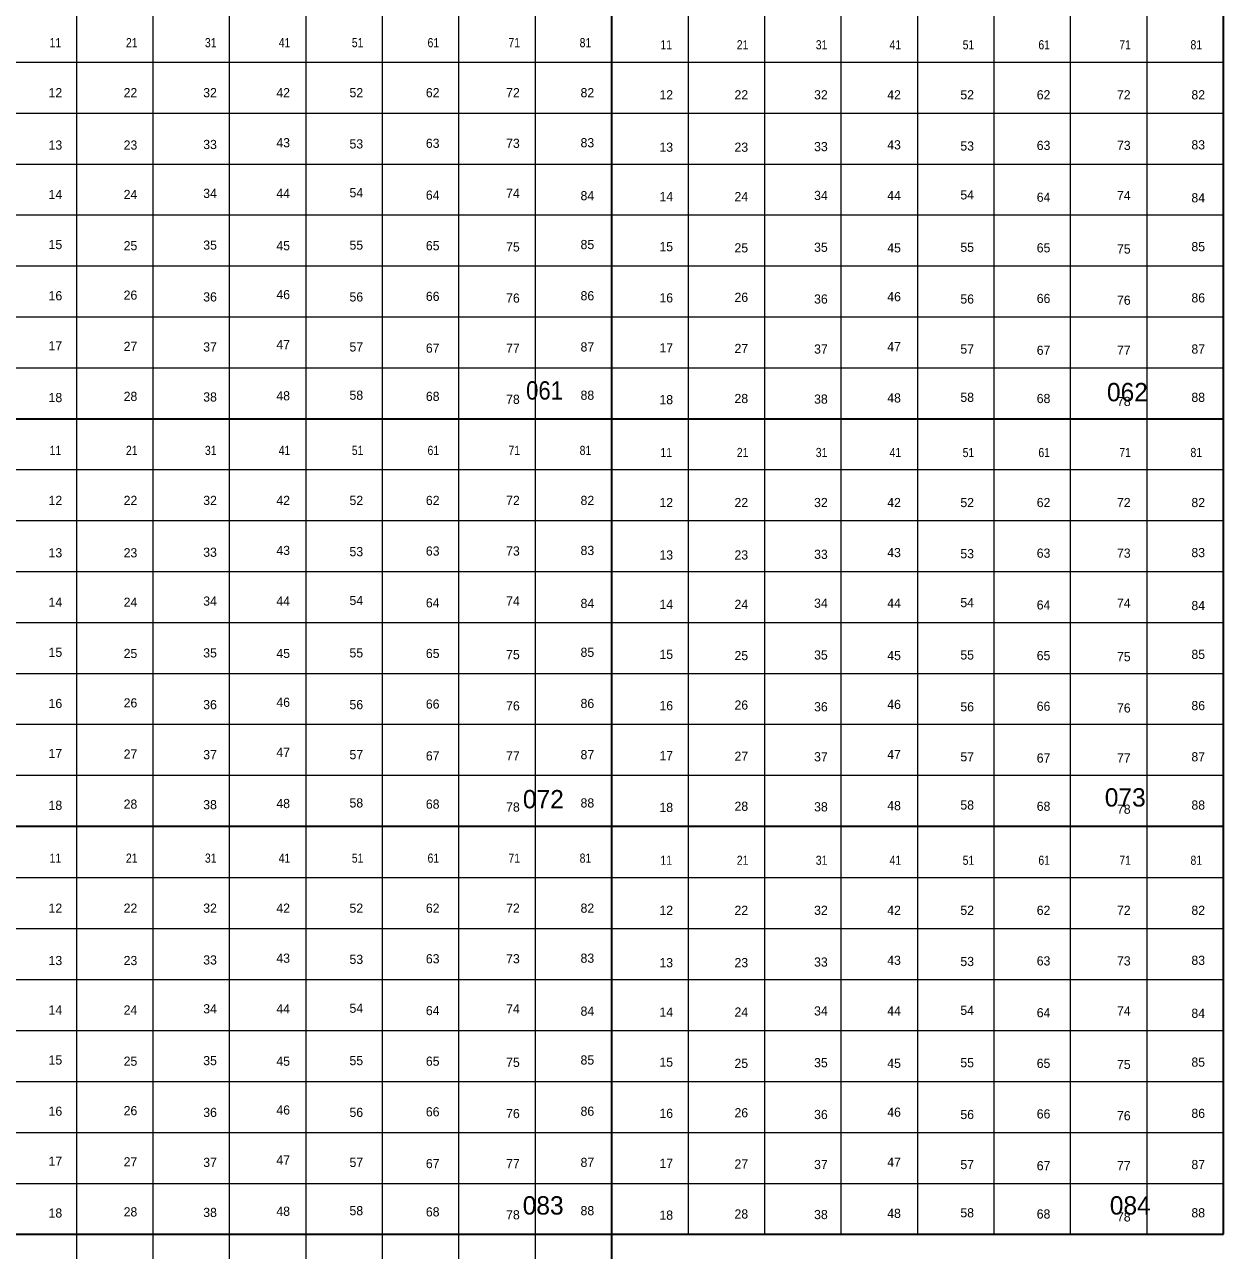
# Model space of a CAD drawing. Extents: x 639000 to 672000, y 222000 to 252000.
# Drawn here: x 666119 to 672000, y 233921 to 239934 of the extents above; entities that cross this region are included whole.
import ezdxf
from ezdxf.enums import TextEntityAlignment as Align

# ---------------------------------------------------------------- set-up
doc = ezdxf.new("R2010")
doc.units = 0
doc.header["$LTSCALE"] = 18
doc.layers.add('1', color=7, linetype='Continuous', lineweight=13)
doc.layers.add('2', color=7, linetype='Continuous')
doc.layers.add('29', color=7, linetype='Continuous')

msp = doc.modelspace()

# ---------------------------------------------------------------- linework, layer by layer
at = {"layer": '1'}
for p, q in [((666375, 230000), (666375, 242000)), ((666750, 230000), (666750, 242000)), ((667125, 230000), (667125, 242000)), ((667500, 230000), (667500, 242000)), ((667875, 230000), (667875, 242000)), ((668250, 230000), (668250, 242000)), ((668625, 230000), (668625, 242000)), ((669375, 234000), (669375, 242000)), ((669750, 234000), (669750, 242000)), ((670125, 234000), (670125, 242000)), ((670500, 234000), (670500, 242000)), ((670875, 234000), (670875, 242000)), ((671250, 234000), (671250, 242000)), ((671625, 234000), (671625, 242000)), ((639000, 239750), (672000, 239750)), ((639000, 239500), (672000, 239500)), ((639000, 239250), (672000, 239250)), ((639000, 239000), (672000, 239000)), ((639000, 238750), (672000, 238750)), ((639000, 238500), (672000, 238500)), ((639000, 238250), (672000, 238250)), ((672000, 237750), (639000, 237750)), ((672000, 237500), (639000, 237500)), ((672000, 237250), (639000, 237250)), ((672000, 237000), (639000, 237000)), ((672000, 236750), (639000, 236750)), ((672000, 236500), (639000, 236500)), ((672000, 236250), (639000, 236250)), ((639000, 235750), (672000, 235750)), ((639000, 235500), (672000, 235500)), ((639000, 235250), (672000, 235250)), ((639000, 235000), (672000, 235000)), ((639000, 234750), (672000, 234750)), ((639000, 234500), (672000, 234500)), ((639000, 234250), (672000, 234250))]:
    msp.add_line(p, q, dxfattribs=at)
at = {"layer": '1', "lineweight": 35}
for p, q in [((669000, 230000), (669000, 242000)), ((672000, 234000), (672000, 242000)), ((639000, 238000), (672000, 238000)), ((672000, 236000), (639000, 236000)), ((639000, 234000), (672000, 234000))]:
    msp.add_line(p, q, dxfattribs=at)

# ---------------------------------------------------------------- texts
at = {"layer": '2', "width": 0.9}
msp.add_text('061', height=90, rotation=359.94, dxfattribs=at).set_placement((668669.64, 238094.39), align=Align.CENTER)
at = {"layer": '2'}
for s, p in [('062', (671528.84, 238086.15)), ('073', (671518.09, 236098.18)), ('084', (671542.74, 234096.82))]:
    msp.add_text(s, height=90, dxfattribs=at).set_placement(p, align=Align.CENTER)
for s, p in [('072', (668663.78, 236089.44)), ('083', (668662.89, 234096.83))]:
    msp.add_text(s, height=90, rotation=359.94, dxfattribs=at).set_placement(p, align=Align.CENTER)
at = {"layer": '29', "width": 0.85}
for s, p in [('11', (666270.2, 239822.77)), ('21', (666644.81, 239822.77)), ('31', (667032.11, 239822.77)), ('41', (667394.01, 239822.77)), ('51', (667752.75, 239822.77)), ('61', (668124.17, 239822.77)), ('71', (668521, 239822.77)), ('81', (668870.21, 239822.77)), ('11', (669266.63, 239812.37)), ('21', (669641.23, 239812.37)), ('31', (670028.53, 239812.37)), ('41', (670390.44, 239812.37)), ('51', (670749.17, 239812.37)), ('61', (671120.6, 239812.37)), ('71', (671517.42, 239812.37)), ('81', (671866.63, 239812.37)), ('11', (666270.2, 237822.77)), ('21', (666644.81, 237822.77)), ('31', (667032.11, 237822.77)), ('41', (667394.01, 237822.77)), ('51', (667752.75, 237822.77)), ('61', (668124.17, 237822.77)), ('71', (668521, 237822.77)), ('81', (668870.21, 237822.77)), ('11', (669266.63, 237812.37)), ('21', (669641.23, 237812.37)), ('31', (670028.53, 237812.37)), ('41', (670390.44, 237812.37)), ('51', (670749.17, 237812.37)), ('61', (671120.6, 237812.37)), ('71', (671517.42, 237812.37)), ('81', (671866.63, 237812.37)), ('11', (666270.2, 235822.77)), ('21', (666644.81, 235822.77)), ('31', (667032.11, 235822.77)), ('41', (667394.01, 235822.77)), ('51', (667752.75, 235822.77)), ('61', (668124.17, 235822.77)), ('71', (668521, 235822.77)), ('81', (668870.21, 235822.77)), ('11', (669266.63, 235812.37)), ('21', (669641.23, 235812.37)), ('31', (670028.53, 235812.37)), ('41', (670390.44, 235812.37)), ('51', (670749.17, 235812.37)), ('61', (671120.6, 235812.37)), ('71', (671517.42, 235812.37)), ('81', (671866.63, 235812.37))]:
    msp.add_text(s, height=45, dxfattribs=at).set_placement(p, align=Align.CENTER)
at = {"layer": '29'}
for s, p in [('12', (666270.2, 239577.38)), ('22', (666638.46, 239577.38)), ('32', (667028.93, 239577.38)), ('42', (667387.66, 239577.38)), ('52', (667746.39, 239577.38)), ('62', (668121, 239577.38)), ('72', (668514.65, 239577.38)), ('82', (668879.73, 239577.38)), ('12', (669266.62, 239566.98)), ('22', (669634.88, 239566.98)), ('32', (670025.36, 239566.98)), ('42', (670384.09, 239566.98)), ('52', (670742.82, 239566.98)), ('62', (671117.42, 239566.98)), ('72', (671511.07, 239566.98)), ('82', (671876.15, 239566.98)), ('13', (666270.2, 239320.44)), ('23', (666638.46, 239320.44)), ('33', (667028.93, 239323.33)), ('43', (667387.67, 239331.99)), ('53', (667746.4, 239326.21)), ('63', (668121, 239329.1)), ('73', (668514.65, 239329.1)), ('83', (668879.73, 239331.99)), ('13', (669266.62, 239310.04)), ('23', (669634.88, 239310.04)), ('33', (670025.36, 239312.93)), ('43', (670384.09, 239321.59)), ('53', (670742.82, 239315.81)), ('63', (671117.42, 239318.7)), ('73', (671511.07, 239318.7)), ('83', (671876.15, 239321.59)), ('14', (666270.2, 239077.93)), ('24', (666638.46, 239077.93)), ('34', (667028.93, 239083.71)), ('44', (667387.67, 239083.71)), ('54', (667746.4, 239086.6)), ('64', (668121, 239075.05)), ('74', (668514.65, 239083.71)), ('84', (668879.73, 239072.16)), ('14', (669266.62, 239067.54)), ('24', (669634.88, 239067.54)), ('34', (670025.36, 239073.31)), ('44', (670384.09, 239073.31)), ('54', (670742.82, 239076.2)), ('64', (671117.42, 239064.65)), ('74', (671511.07, 239073.31)), ('84', (671876.15, 239061.76)), ('15', (666270.2, 238832.54)), ('25', (666638.46, 238826.77)), ('35', (667028.93, 238829.66)), ('45', (667387.67, 238826.77)), ('55', (667746.4, 238829.66)), ('65', (668121, 238826.77)), ('75', (668514.65, 238821)), ('85', (668879.73, 238832.55)), ('15', (669266.62, 238822.14)), ('25', (669634.88, 238816.37)), ('35', (670025.36, 238819.26)), ('45', (670384.09, 238816.37)), ('55', (670742.82, 238819.26)), ('65', (671117.42, 238816.37)), ('85', (671876.15, 238822.15)), ('75', (671511.07, 238810.6)), ('16', (666270.2, 238581.38)), ('26', (666638.46, 238584.27)), ('36', (667028.93, 238575.61)), ('46', (667387.67, 238587.15)), ('56', (667746.4, 238575.61)), ('66', (668121, 238578.49)), ('86', (668879.73, 238581.38)), ('26', (669634.88, 238573.87)), ('46', (670384.09, 238576.75)), ('76', (668514.65, 238569.83)), ('16', (669266.62, 238570.98)), ('36', (670025.36, 238565.21)), ('56', (670742.82, 238565.21)), ('66', (671117.42, 238568.09)), ('76', (671511.07, 238559.43)), ('86', (671876.15, 238570.98)), ('17', (666270.2, 238335.99)), ('27', (666638.46, 238333.1)), ('47', (667387.67, 238341.76)), ('47', (670384.09, 238331.36)), ('37', (667028.93, 238330.22)), ('57', (667746.4, 238330.22)), ('67', (668121, 238324.44)), ('77', (668514.65, 238324.44)), ('87', (668879.73, 238330.22)), ('17', (669266.63, 238325.59)), ('27', (669634.88, 238322.7)), ('37', (670025.36, 238319.82)), ('57', (670742.82, 238319.82)), ('67', (671117.42, 238314.04)), ('77', (671511.07, 238314.04)), ('87', (671876.15, 238319.82)), ('48', (667387.66, 238090.6)), ('58', (667746.39, 238093.49)), ('88', (668879.73, 238093.49)), ('18', (666270.2, 238081.94)), ('28', (666638.46, 238087.71)), ('38', (667028.93, 238084.83)), ('68', (668121, 238087.71)), ('78', (668514.65, 238073.28)), ('18', (669266.62, 238071.54)), ('28', (669634.88, 238077.31)), ('38', (670025.36, 238074.43)), ('48', (670384.09, 238080.2)), ('58', (670742.82, 238083.09)), ('68', (671117.42, 238077.31)), ('78', (671511.07, 238062.88)), ('88', (671876.15, 238083.09)), ('12', (666270.2, 237577.38)), ('22', (666638.46, 237577.38)), ('32', (667028.93, 237577.38)), ('42', (667387.66, 237577.38)), ('52', (667746.39, 237577.38)), ('62', (668121, 237577.38)), ('72', (668514.65, 237577.38)), ('82', (668879.73, 237577.38)), ('12', (669266.62, 237566.98)), ('22', (669634.88, 237566.98)), ('32', (670025.36, 237566.98)), ('42', (670384.09, 237566.98)), ('52', (670742.82, 237566.98)), ('62', (671117.42, 237566.98)), ('72', (671511.07, 237566.98)), ('82', (671876.15, 237566.98)), ('13', (666270.2, 237320.44)), ('23', (666638.46, 237320.44)), ('33', (667028.93, 237323.33)), ('43', (667387.67, 237331.99)), ('53', (667746.4, 237326.21)), ('63', (668121, 237329.1)), ('73', (668514.65, 237329.1)), ('83', (668879.73, 237331.99)), ('13', (669266.62, 237310.04)), ('23', (669634.88, 237310.04)), ('33', (670025.36, 237312.93)), ('43', (670384.09, 237321.59)), ('53', (670742.82, 237315.81)), ('63', (671117.42, 237318.7)), ('73', (671511.07, 237318.7)), ('83', (671876.15, 237321.59)), ('14', (666270.2, 237077.93)), ('24', (666638.46, 237077.93)), ('34', (667028.93, 237083.71)), ('44', (667387.67, 237083.71)), ('54', (667746.4, 237086.6)), ('64', (668121, 237075.05)), ('74', (668514.65, 237083.71)), ('84', (668879.73, 237072.16)), ('34', (670025.36, 237073.31)), ('44', (670384.09, 237073.31)), ('54', (670742.82, 237076.2)), ('74', (671511.07, 237073.31)), ('14', (669266.62, 237067.54)), ('24', (669634.88, 237067.54)), ('64', (671117.42, 237064.65)), ('84', (671876.15, 237061.76)), ('15', (666270.2, 236832.54)), ('35', (667028.93, 236829.66)), ('55', (667746.4, 236829.66)), ('85', (668879.73, 236832.55)), ('25', (666638.46, 236826.77)), ('45', (667387.67, 236826.77)), ('65', (668121, 236826.77)), ('75', (668514.65, 236821)), ('15', (669266.62, 236822.14)), ('25', (669634.88, 236816.37)), ('35', (670025.36, 236819.26)), ('45', (670384.09, 236816.37)), ('55', (670742.82, 236819.26)), ('65', (671117.42, 236816.37)), ('75', (671511.07, 236810.6)), ('85', (671876.15, 236822.15)), ('46', (667387.67, 236587.15)), ('16', (666270.2, 236581.38)), ('26', (666638.46, 236584.27)), ('36', (667028.93, 236575.61)), ('56', (667746.4, 236575.61)), ('66', (668121, 236578.49)), ('76', (668514.65, 236569.83)), ('86', (668879.73, 236581.38)), ('16', (669266.62, 236570.98)), ('26', (669634.88, 236573.87)), ('36', (670025.36, 236565.21)), ('46', (670384.09, 236576.75)), ('56', (670742.82, 236565.21)), ('66', (671117.42, 236568.09)), ('76', (671511.07, 236559.43)), ('86', (671876.15, 236570.98)), ('17', (666270.2, 236335.99)), ('27', (666638.46, 236333.1)), ('37', (667028.93, 236330.22)), ('47', (667387.67, 236341.76)), ('57', (667746.4, 236330.22)), ('67', (668121, 236324.44)), ('77', (668514.65, 236324.44)), ('87', (668879.73, 236330.22)), ('17', (669266.63, 236325.59)), ('27', (669634.88, 236322.7)), ('37', (670025.36, 236319.82)), ('47', (670384.09, 236331.36)), ('57', (670742.82, 236319.82)), ('67', (671117.42, 236314.04)), ('77', (671511.07, 236314.04)), ('87', (671876.15, 236319.82)), ('18', (666270.2, 236081.94)), ('28', (666638.46, 236087.71)), ('38', (667028.93, 236084.83)), ('48', (667387.66, 236090.6)), ('58', (667746.39, 236093.49)), ('68', (668121, 236087.71)), ('78', (668514.65, 236073.28)), ('88', (668879.73, 236093.49)), ('18', (669266.62, 236071.54)), ('28', (669634.88, 236077.31)), ('38', (670025.36, 236074.43)), ('48', (670384.09, 236080.2)), ('58', (670742.82, 236083.09)), ('68', (671117.42, 236077.31)), ('78', (671511.07, 236062.88)), ('88', (671876.15, 236083.09)), ('12', (666270.2, 235577.38)), ('22', (666638.46, 235577.38)), ('32', (667028.93, 235577.38)), ('42', (667387.66, 235577.38)), ('52', (667746.39, 235577.38)), ('62', (668121, 235577.38)), ('72', (668514.65, 235577.38)), ('82', (668879.73, 235577.38)), ('12', (669266.62, 235566.98)), ('22', (669634.88, 235566.98)), ('32', (670025.36, 235566.98)), ('42', (670384.09, 235566.98)), ('52', (670742.82, 235566.98)), ('62', (671117.42, 235566.98)), ('72', (671511.07, 235566.98)), ('82', (671876.15, 235566.98)), ('43', (667387.67, 235331.99)), ('53', (667746.4, 235326.21)), ('63', (668121, 235329.1)), ('73', (668514.65, 235329.1)), ('83', (668879.73, 235331.99)), ('13', (666270.2, 235320.44)), ('23', (666638.46, 235320.44)), ('33', (667028.93, 235323.33)), ('13', (669266.62, 235310.04)), ('23', (669634.88, 235310.04)), ('33', (670025.36, 235312.93)), ('43', (670384.09, 235321.59)), ('53', (670742.82, 235315.81)), ('63', (671117.42, 235318.7)), ('73', (671511.07, 235318.7)), ('83', (671876.15, 235321.59)), ('34', (667028.93, 235083.71)), ('54', (667746.4, 235086.6)), ('14', (666270.2, 235077.93)), ('24', (666638.46, 235077.93)), ('44', (667387.67, 235083.71)), ('64', (668121, 235075.05)), ('74', (668514.65, 235083.71)), ('84', (668879.73, 235072.16)), ('14', (669266.62, 235067.54)), ('24', (669634.88, 235067.54)), ('34', (670025.36, 235073.31)), ('44', (670384.09, 235073.31)), ('54', (670742.82, 235076.2)), ('64', (671117.42, 235064.65)), ('74', (671511.07, 235073.31)), ('84', (671876.15, 235061.76)), ('15', (666270.2, 234832.54)), ('25', (666638.46, 234826.77)), ('35', (667028.93, 234829.66)), ('45', (667387.67, 234826.77)), ('55', (667746.4, 234829.66)), ('65', (668121, 234826.77)), ('75', (668514.65, 234821)), ('85', (668879.73, 234832.55)), ('15', (669266.62, 234822.14)), ('25', (669634.88, 234816.37)), ('35', (670025.36, 234819.26)), ('45', (670384.09, 234816.37)), ('55', (670742.82, 234819.26)), ('65', (671117.42, 234816.37)), ('75', (671511.07, 234810.6)), ('85', (671876.15, 234822.15)), ('16', (666270.2, 234581.38)), ('26', (666638.46, 234584.27)), ('36', (667028.93, 234575.61)), ('46', (667387.67, 234587.15)), ('56', (667746.4, 234575.61)), ('66', (668121, 234578.49)), ('76', (668514.65, 234569.83)), ('86', (668879.73, 234581.38)), ('16', (669266.62, 234570.98)), ('26', (669634.88, 234573.87)), ('36', (670025.36, 234565.21)), ('46', (670384.09, 234576.75)), ('56', (670742.82, 234565.21)), ('66', (671117.42, 234568.09)), ('76', (671511.07, 234559.43)), ('86', (671876.15, 234570.98)), ('17', (666270.2, 234335.99)), ('27', (666638.46, 234333.1)), ('37', (667028.93, 234330.22)), ('47', (667387.67, 234341.76)), ('57', (667746.4, 234330.22)), ('67', (668121, 234324.44)), ('77', (668514.65, 234324.44)), ('87', (668879.73, 234330.22)), ('17', (669266.63, 234325.59)), ('27', (669634.88, 234322.7)), ('37', (670025.36, 234319.82)), ('47', (670384.09, 234331.36)), ('57', (670742.82, 234319.82)), ('67', (671117.42, 234314.04)), ('77', (671511.07, 234314.04)), ('87', (671876.15, 234319.82)), ('18', (666270.2, 234081.94)), ('28', (666638.46, 234087.71)), ('38', (667028.93, 234084.83)), ('48', (667387.66, 234090.6)), ('58', (667746.39, 234093.49)), ('68', (668121, 234087.71)), ('78', (668514.65, 234073.28)), ('88', (668879.73, 234093.49)), ('18', (669266.62, 234071.54)), ('28', (669634.88, 234077.31)), ('38', (670025.36, 234074.43)), ('48', (670384.09, 234080.2)), ('58', (670742.82, 234083.09)), ('68', (671117.42, 234077.31)), ('78', (671511.07, 234062.88)), ('88', (671876.15, 234083.09))]:
    msp.add_text(s, height=45, dxfattribs=at).set_placement(p, align=Align.CENTER)

doc.saveas('drawing.dxf')
